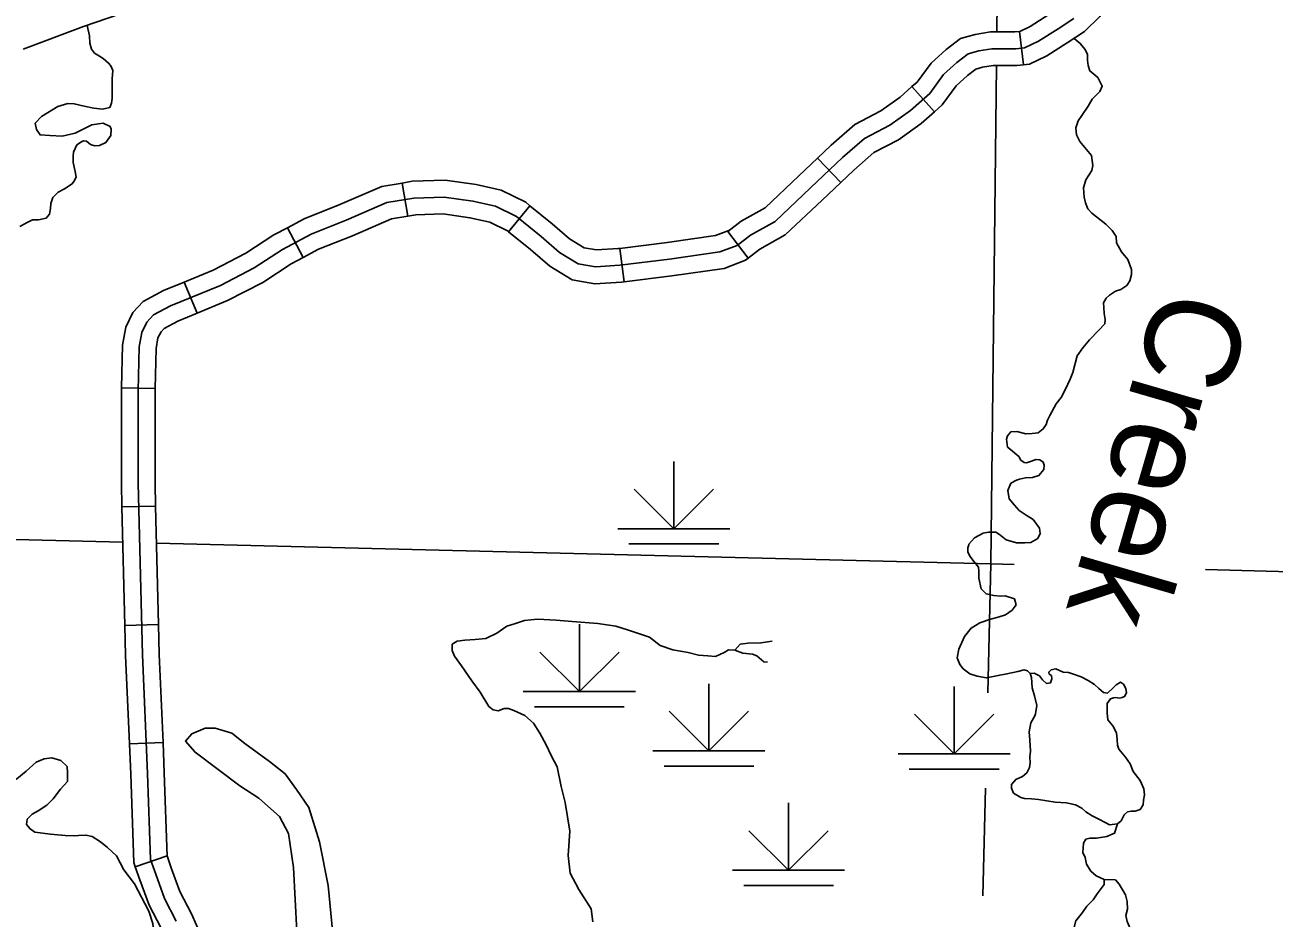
# Model space of a CAD drawing. Extents: x 8749 to 11879, y 13275 to 15339.
# Drawn here: x 10444.5 to 10555.9, y 13724.7 to 13804.4 of the extents above; entities that cross this region are included whole.
import ezdxf

# ---------------------------------------------------------------- set-up
doc = ezdxf.new("R2010")
doc.units = 0
for name, color, linetype in [('Level 15', 7, 'Continuous'), ('Level 32', 7, 'Continuous'), ('Level 35', 7, 'Continuous'), ('Level 44', 7, 'Continuous'), ('Level 5', 7, 'Continuous')]:
    doc.layers.add(name, color=color, linetype=linetype)

msp = doc.modelspace()

# ---------------------------------------------------------------- linework, layer by layer
at = {"layer": 'Level 15'}
for points in [[(10449.72, 13804.25), (10452.92, 13805.35), (10454.17, 13805.76)], [(10444.35, 13802.22), (10449.72, 13804.25)]]:
    msp.add_lwpolyline(points, dxfattribs=at)
at = {"layer": 'Level 32'}
for p, q in [((10533.55, 13800.84), (10533.2, 13803.82)), ((10525.6, 13796.65), (10523.6, 13798.89)), ((10517.25, 13790.35), (10515.18, 13792.52)), ((10478.64, 13787.34), (10478.14, 13790.29)), ((10487.63, 13785.94), (10489.53, 13788.27)), ((10469.31, 13783.66), (10467.9, 13786.3)), ((10509, 13783.59), (10507.17, 13785.97)), ((10497.92, 13781.48), (10497.55, 13784.46)), ((10459.86, 13778.68), (10458.71, 13781.46)), ((10456.11, 13771.95), (10453.11, 13772.02)), ((10456.15, 13761.46), (10453.15, 13761.39)), ((10456.4, 13750.9), (10453.4, 13750.83)), ((10456.81, 13740.38), (10453.81, 13740.25)), ((10457.18, 13730.26), (10454.34, 13729.29))]:
    msp.add_line(p, q, dxfattribs=at)
for points in [[(10533.2, 13803.82), (10533.22, 13803.82), (10534.15, 13804.27), (10535.81, 13805.32), (10537.1, 13806.15), (10538, 13807.04), (10538.52, 13807.87), (10539.06, 13809.4), (10539.13, 13809.7)], [(10533.55, 13800.84), (10534.07, 13800.9), (10535.61, 13801.64), (10537.43, 13802.79), (10538.98, 13803.8), (10540.35, 13805.14), (10541.24, 13806.55), (10541.94, 13808.55), (10542.05, 13809)], [(10523.6, 13798.89), (10524.06, 13799.3), (10525.3, 13800.99), (10526.65, 13802.19), (10527.92, 13803.18), (10529.24, 13803.55), (10530.6, 13803.77), (10531.68, 13803.77), (10532.78, 13803.77), (10533.2, 13803.82)], [(10525.6, 13796.65), (10526.29, 13797.27), (10527.53, 13798.96), (10528.56, 13799.88), (10529.3, 13800.45), (10529.9, 13800.62), (10530.83, 13800.77), (10531.68, 13800.77), (10532.95, 13800.77), (10533.55, 13800.84)], [(10515.18, 13792.52), (10516.39, 13793.67), (10518.51, 13795.5), (10520.82, 13796.72), (10522.55, 13797.95), (10523.6, 13798.89)], [(10517.25, 13790.35), (10518.4, 13791.44), (10520.21, 13793.01), (10522.39, 13794.16), (10524.42, 13795.6), (10525.6, 13796.65)], [(10507.17, 13785.97), (10508.37, 13786.89), (10510.5, 13788.09), (10513.52, 13790.94), (10515.18, 13792.52)], [(10478.14, 13790.29), (10479.03, 13790.45), (10481.97, 13790.55), (10484.72, 13790.15), (10486.96, 13789.64), (10489.15, 13788.57), (10489.53, 13788.27)], [(10467.9, 13786.3), (10469.39, 13787.1), (10472.57, 13788.37), (10476.33, 13789.99), (10478.14, 13790.29)], [(10509, 13783.59), (10510.03, 13784.38), (10512.29, 13785.66), (10515.59, 13788.76), (10517.25, 13790.35)], [(10489.53, 13788.27), (10491.5, 13786.66), (10493.07, 13785.31), (10494.37, 13784.51), (10495.47, 13784.32), (10497.4, 13784.44), (10497.55, 13784.46)], [(10469.31, 13783.66), (10470.66, 13784.38), (10473.71, 13785.59), (10477.19, 13787.09), (10478.64, 13787.34)], [(10478.64, 13787.34), (10479.34, 13787.45), (10481.8, 13787.54), (10484.18, 13787.2), (10485.96, 13786.79), (10487.53, 13786.03), (10487.63, 13785.94)], [(10458.71, 13781.46), (10461.29, 13782.52), (10464.19, 13784.02), (10466.7, 13785.66), (10467.9, 13786.3)], [(10487.63, 13785.94), (10489.57, 13784.36), (10491.3, 13782.88), (10493.29, 13781.66), (10495.31, 13781.3), (10497.68, 13781.45), (10497.92, 13781.48)], [(10497.55, 13784.46), (10501.78, 13784.98), (10506.09, 13785.6), (10507.28, 13786.06), (10507.17, 13785.97)], [(10459.86, 13778.68), (10462.56, 13779.8), (10465.7, 13781.42), (10468.23, 13783.08), (10469.31, 13783.66)], [(10497.92, 13781.48), (10502.18, 13782.01), (10506.85, 13782.68), (10508.76, 13783.41), (10509, 13783.59)], [(10453.11, 13772.02), (10453.2, 13775.83), (10453.48, 13777.44), (10454.13, 13778.75), (10455.05, 13779.73), (10456.85, 13780.69), (10458.71, 13781.46)], [(10456.11, 13771.95), (10456.19, 13775.53), (10456.36, 13776.49), (10456.63, 13777.02), (10456.9, 13777.32), (10458.12, 13777.97), (10459.86, 13778.68)], [(10453.15, 13761.39), (10453.1, 13763.48), (10453.1, 13771.76), (10453.11, 13772.02)], [(10456.15, 13761.46), (10456.1, 13763.51), (10456.1, 13771.73), (10456.11, 13771.95)], [(10456.4, 13750.9), (10456.15, 13761.46)], [(10453.4, 13750.83), (10453.15, 13761.39)], [(10453.81, 13740.25), (10453.47, 13748.14), (10453.4, 13750.83)], [(10456.81, 13740.38), (10456.47, 13748.24), (10456.4, 13750.9)], [(10457.19, 13730.23), (10456.92, 13737.66), (10456.81, 13740.38)], [(10454.34, 13729.29), (10454.21, 13729.67), (10453.93, 13737.54), (10453.81, 13740.25)], [(10461.26, 13720.6), (10460.7, 13722.05), (10459.34, 13725.1), (10458.31, 13727.07), (10457.57, 13729.12), (10457.18, 13730.26)], [(10458.46, 13719.52), (10457.93, 13720.9), (10456.64, 13723.8), (10455.56, 13725.86), (10454.74, 13728.12), (10454.34, 13729.29)]]:
    msp.add_lwpolyline(points, dxfattribs=at)
at = {"layer": 'Level 35'}
for points in [[(10457.99, 13724.45), (10456.94, 13726.47), (10456.16, 13728.62), (10455.7, 13729.95), (10455.43, 13737.6), (10454.97, 13748.19), (10454.6, 13763.5), (10454.6, 13771.74), (10454.69, 13775.68), (10454.92, 13776.97), (10455.38, 13777.88), (10455.97, 13778.53), (10457.49, 13779.33), (10461.93, 13781.16), (10464.95, 13782.72), (10467.46, 13784.37), (10470.03, 13785.74), (10473.14, 13786.98), (10476.76, 13788.54), (10479.18, 13788.95), (10481.88, 13789.04), (10484.45, 13788.68), (10486.46, 13788.22), (10488.34, 13787.3), (10490.54, 13785.51), (10492.18, 13784.09), (10493.83, 13783.08), (10495.39, 13782.81), (10497.54, 13782.95), (10501.98, 13783.5), (10506.47, 13784.14), (10508.02, 13784.73), (10509.2, 13785.64), (10511.4, 13786.87), (10514.56, 13789.85), (10517.39, 13792.56), (10519.36, 13794.25), (10521.61, 13795.44), (10523.48, 13796.77), (10525.18, 13798.28), (10526.41, 13799.98), (10527.6, 13801.03), (10528.61, 13801.81), (10529.57, 13802.09), (10530.72, 13802.27), (10531.68, 13802.27), (10532.87, 13802.27), (10533.64, 13802.36), (10534.88, 13802.96), (10536.62, 13804.06), (10538.04, 13804.97)], [(10452.11, 13795.32), (10451.48, 13795.62), (10450.46, 13795.49), (10448.99, 13794.74), (10447.81, 13794.47), (10446.72, 13794.52), (10445.84, 13794.59), (10445.52, 13795.07), (10445.42, 13795.62), (10445.97, 13796.24), (10447.44, 13797.12), (10448.31, 13797.39), (10448.89, 13797.37), (10449.79, 13797.14), (10450.64, 13796.97), (10451.41, 13796.87), (10452.06, 13797.02), (10452.21, 13797.42), (10452.26, 13797.84), (10452.26, 13798.57), (10452.26, 13799.59), (10452.33, 13800.34), (10452.16, 13800.74), (10451.96, 13800.99), (10451.48, 13801.39), (10451.14, 13801.62), (10450.71, 13801.87), (10450.44, 13802.22), (10450.29, 13802.77), (10450.26, 13803.42), (10450.04, 13804.36)], [(10538.74, 13796.33), (10539.3, 13797.15), (10539.68, 13797.76), (10540.36, 13798.47), (10540.56, 13798.92), (10540.16, 13799.71), (10539.47, 13800.29), (10539.3, 13800.77), (10539.25, 13801.25), (10539.25, 13801.79), (10539.02, 13802.24), (10538.61, 13802.75), (10538.06, 13803.2)], [(10540.89, 13786.62), (10539.65, 13787.59), (10539.27, 13788), (10539.07, 13788.51), (10538.94, 13789.04), (10538.89, 13789.87), (10539.09, 13790.58), (10539.65, 13791.42), (10539.73, 13791.85), (10539.6, 13792.74), (10539.17, 13793.29), (10538.56, 13794), (10538.26, 13794.59), (10538.21, 13795.22), (10538.41, 13795.85), (10538.74, 13796.33)], [(10448.97, 13791.33), (10448.81, 13792.12), (10448.81, 13792.39), (10448.81, 13792.69), (10448.84, 13793.04), (10449.11, 13793.69), (10449.54, 13793.97), (10449.71, 13794.07), (10449.99, 13794.02), (10450.34, 13793.72), (10450.74, 13793.62), (10451.14, 13793.64), (10451.71, 13793.92), (10452.16, 13794.52), (10452.18, 13795.09), (10452.11, 13795.32)], [(10444.03, 13786.41), (10444.68, 13786.76), (10445.18, 13787.01), (10445.7, 13787.01), (10446.4, 13787.16), (10446.7, 13787.51), (10446.77, 13788.01), (10446.8, 13788.46), (10446.97, 13789.01), (10447.47, 13789.48), (10448.02, 13789.76), (10448.7, 13790.21), (10448.87, 13790.43), (10449.07, 13790.81), (10448.97, 13791.33)], [(10537.7, 13772.79), (10537.93, 13773.39), (10538.33, 13774.86), (10538.84, 13775.6), (10539.42, 13776.31), (10540.26, 13777.17), (10540.79, 13777.73), (10540.82, 13778.13), (10540.74, 13778.64), (10540.71, 13779.19), (10540.69, 13779.6), (10540.92, 13780.03), (10541.22, 13780.28), (10541.75, 13780.64), (10542.21, 13780.79), (10542.76, 13781.15), (10543.02, 13781.58), (10543.17, 13782.13), (10543.17, 13782.59), (10542.84, 13783.48), (10542.28, 13784.16), (10541.85, 13784.97), (10541.8, 13785.53), (10541.45, 13786.06), (10540.89, 13786.62)], [(10535.88, 13769.55), (10536.46, 13770.59), (10536.89, 13771.17), (10537.3, 13771.91), (10537.7, 13772.79)], [(10533.13, 13765.89), (10532.39, 13766.51), (10532.13, 13766.74), (10532.03, 13767.45), (10532.11, 13767.75), (10532.41, 13768.08), (10532.94, 13768.13), (10533.75, 13767.93), (10534.31, 13767.96), (10534.84, 13768.01), (10535.3, 13768.36), (10535.55, 13768.74), (10535.68, 13769.12), (10535.88, 13769.55)], [(10532.75, 13753.18), (10531.91, 13753.45), (10531.53, 13753.43), (10530.9, 13753.5), (10530.21, 13753.63), (10529.78, 13754.09), (10529.56, 13755.05), (10529.56, 13755.66), (10529.53, 13756.01), (10529.15, 13756.49), (10528.75, 13757), (10528.59, 13757.38), (10528.57, 13757.74), (10528.67, 13758.01), (10528.67, 13758.07), (10529.18, 13758.65), (10529.94, 13759.05), (10530.42, 13759.13), (10530.72, 13759.15), (10531.08, 13759.15), (10531.4, 13758.93), (10531.99, 13758.47), (10532.92, 13758.19), (10533.66, 13758.19), (10534.19, 13758.22), (10534.82, 13758.57), (10535.02, 13759.03), (10534.97, 13759.51), (10534.42, 13760.27), (10533.78, 13760.67), (10533.15, 13761.08), (10532.75, 13761.54), (10532.26, 13762.12), (10532.14, 13762.85), (10532.42, 13763.51), (10532.92, 13763.79), (10533.2, 13763.87), (10533.71, 13763.99), (10534.34, 13764.02), (10534.92, 13764.2), (10535.35, 13764.73), (10535.4, 13765.11), (10535.3, 13765.39), (10535, 13765.59), (10534.64, 13765.64), (10534.26, 13765.49), (10533.81, 13765.34), (10533.61, 13765.36), (10533.3, 13765.56), (10533.13, 13765.89)], [(10531.29, 13746.35), (10530.23, 13746.14), (10529.4, 13746.3), (10528.77, 13746.5), (10528.17, 13746.95), (10527.86, 13747.35), (10527.64, 13747.94), (10527.79, 13748.69), (10528.29, 13749.83), (10528.87, 13750.58), (10529.65, 13751.06), (10530.59, 13751.39), (10531.29, 13751.57), (10531.95, 13751.77), (10532.53, 13752.17), (10532.88, 13752.65), (10532.75, 13753.18)], [(10482.6, 13749.14), (10483.03, 13749.43), (10483.71, 13749.51), (10484.64, 13749.56), (10485.6, 13749.66), (10486.58, 13750.14), (10487.46, 13750.75), (10488.24, 13751), (10489.05, 13751.25), (10489.61, 13751.33), (10490.21, 13751.38), (10491.87, 13751.28), (10493.29, 13751.18), (10495.58, 13751), (10497.19, 13750.77), (10498.23, 13750.42), (10500.19, 13749.76), (10501.15, 13749.03), (10502.28, 13748.63), (10503.65, 13748.4), (10504.55, 13748.17), (10505.38, 13748.12), (10506.07, 13748.05), (10506.85, 13748.4), (10507.25, 13748.65), (10507.8, 13748.6), (10508.51, 13748.35), (10509.39, 13748.27), (10509.75, 13748.12), (10510.4, 13747.57), (10510.7, 13747.54)], [(10507.8, 13748.6), (10508.28, 13749.16), (10508.99, 13749.23), (10510.12, 13749.26), (10511.13, 13749.43)], [(10491.41, 13739.22), (10490.97, 13740.16), (10490.42, 13741.22), (10489.86, 13742.1), (10489.08, 13742.79), (10488.1, 13743.24), (10487.62, 13743.42), (10487.24, 13743.42), (10486.71, 13743.19), (10486.26, 13743.29), (10485.86, 13743.59), (10485.1, 13744.88), (10484.34, 13745.89), (10483.44, 13747.23), (10482.81, 13748.08), (10482.6, 13748.59), (10482.6, 13749.14)], [(10541.9, 13740.61), (10541.85, 13741.23), (10541.5, 13741.86), (10541.07, 13742.39), (10541, 13743.02), (10541, 13743.86), (10541.3, 13744.26), (10541.58, 13744.36), (10541.75, 13744.38), (10542.1, 13744.33), (10542.33, 13744.38), (10542.56, 13744.49), (10542.74, 13744.81), (10542.68, 13745.19), (10542.46, 13745.57), (10542.18, 13745.75), (10541.8, 13745.52), (10541.5, 13745.22), (10541.02, 13744.79), (10540.67, 13744.84), (10540.26, 13745.19), (10539.86, 13745.55), (10539.31, 13745.9), (10538.7, 13746.23), (10538, 13746.48), (10537.57, 13746.61), (10537.09, 13746.66), (10536.43, 13746.96), (10536.01, 13746.86), (10535.8, 13746.66), (10535.83, 13746.48), (10536.03, 13746.35), (10536.06, 13746.05), (10535.95, 13745.7), (10535.6, 13745.65), (10535.25, 13745.97), (10534.97, 13746.33), (10534.49, 13746.55), (10534.14, 13746.53)], [(10534.62, 13742.93), (10534.74, 13743.68), (10534.52, 13744.54), (10534.32, 13745.24), (10534.27, 13746.18), (10534.14, 13746.53), (10533.89, 13746.76), (10533.61, 13746.86), (10533.03, 13746.71), (10532.07, 13746.5), (10531.29, 13746.35)], [(10534.16, 13739.6), (10534.11, 13740.59), (10534.06, 13741.34), (10534.19, 13742.12), (10534.54, 13742.75), (10534.62, 13742.93)], [(10466.31, 13738.67), (10464.11, 13740.3), (10462.96, 13741.2), (10461.46, 13741.65), (10460.56, 13741.65), (10459.37, 13741.15), (10458.82, 13740.5), (10459.67, 13739.5), (10463.66, 13736.5), (10465.36, 13735.42)], [(10541.93, 13733.13), (10542.25, 13733.4), (10542.53, 13733.93), (10542.83, 13734.18), (10543.14, 13734.25), (10543.51, 13734.25), (10543.94, 13734.41), (10544.22, 13734.83), (10544.24, 13735.24), (10544.32, 13735.72), (10544.27, 13736.25), (10543.94, 13737), (10543.31, 13737.79), (10543.06, 13738.47), (10542.63, 13739.07), (10542.05, 13739.78), (10541.93, 13740.13), (10541.9, 13740.61)], [(10491.41, 13739.22), (10491.97, 13738.21), (10492.32, 13736.44), (10492.67, 13735.03), (10493.08, 13732.46), (10492.93, 13730.29), (10493.13, 13728.72), (10493.88, 13727.26), (10494.99, 13725.55), (10495.14, 13724.38)], [(10536.36, 13735.04), (10534.89, 13735.29), (10534.26, 13735.34), (10533.63, 13735.39), (10533.31, 13735.47), (10532.65, 13735.87), (10532.47, 13736.3), (10532.47, 13736.63), (10532.85, 13737.08), (10533.46, 13737.33), (10533.83, 13737.66), (10534.09, 13738.14), (10534.14, 13738.57), (10534.11, 13739.1), (10534.16, 13739.6), (10534.19, 13739.63)], [(10444.65, 13733.06), (10444.7, 13733.53), (10445.15, 13733.98), (10445.67, 13734.28), (10446.45, 13734.78), (10447.02, 13735.36), (10447.67, 13736.2), (10448.3, 13736.9), (10448.3, 13737.68), (10448.27, 13738.23), (10447.7, 13738.78), (10446.9, 13739), (10446.2, 13738.93), (10445.5, 13738.63), (10444.6, 13737.83), (10443.78, 13737.15), (10442.8, 13736.68), (10441.88, 13736.6), (10441.06, 13736.63), (10440.36, 13736.65), (10439.76, 13736.8)], [(10468.45, 13729.23), (10468.75, 13723.53), (10468.1, 13717.28), (10467.41, 13713.88), (10467.56, 13712.38), (10468.4, 13711.73), (10469.45, 13711.78), (10471.05, 13713.13), (10472, 13717.13), (10472.15, 13721.13), (10471.55, 13727.63), (10470.75, 13731.52), (10469.8, 13734.57), (10468.7, 13736.17), (10467.7, 13737.57), (10466.31, 13738.67)], [(10468.45, 13729.23), (10468, 13732.27), (10467.21, 13733.77), (10465.36, 13735.42)], [(10541.93, 13733.13), (10541.2, 13733.04), (10540.94, 13733.19), (10540.14, 13733.6), (10539.68, 13733.83), (10539.1, 13734.2), (10538.75, 13734.53), (10538.17, 13734.81), (10537.77, 13734.91), (10537.39, 13734.99), (10536.86, 13735.01), (10536.36, 13735.04)], [(10446.79, 13732.19), (10445.38, 13732.38), (10444.95, 13732.66), (10444.65, 13733.06)], [(10540.74, 13728.14), (10540.01, 13728.48), (10539.56, 13728.89), (10539.15, 13729.52), (10539.03, 13730.12), (10538.83, 13730.55), (10538.88, 13731.41), (10539.1, 13731.74), (10539.46, 13731.84), (10540.06, 13731.84), (10540.97, 13731.99), (10541.67, 13732.29), (10541.93, 13733.13)], [(10456.03, 13719.34), (10455.43, 13720.6), (10455.32, 13721.8), (10455.56, 13722.94), (10455.81, 13723.54), (10455.93, 13723.89), (10455.9, 13724.22), (10455.53, 13725.32), (10454.28, 13727.77), (10453.31, 13729.02), (10452.66, 13730.27), (10451.86, 13731.01), (10451.24, 13731.51), (10450.48, 13731.98), (10449.94, 13732.11), (10449.26, 13732.08), (10448.94, 13732.06), (10448.09, 13732.08), (10446.79, 13732.19)], [(10537.97, 13723.55), (10538.22, 13724.48), (10538.8, 13725.22), (10539.18, 13725.77), (10539.76, 13726.33), (10540.11, 13726.88), (10540.74, 13727.71), (10540.74, 13728.14)], [(10541.75, 13728.12), (10540.74, 13728.14)], [(10544.19, 13716.77), (10544.87, 13718.1), (10545, 13718.61), (10545, 13719.01), (10544.9, 13719.39), (10544.7, 13719.67), (10544.52, 13720.14), (10544.47, 13720.4), (10544.47, 13721.48), (10544.37, 13722.06), (10544.04, 13722.59), (10543.59, 13723.02), (10543.18, 13723.53), (10542.78, 13724.41), (10542.68, 13724.94), (10542.83, 13725.52), (10542.78, 13726.2), (10542.63, 13726.78), (10542.35, 13727.29), (10542.07, 13727.74), (10541.75, 13728.12)]]:
    msp.add_lwpolyline(points, dxfattribs=at)
at = {"layer": 'Level 44'}
for p, q in [((10502.36, 13765.45), (10502.36, 13759.45)), ((10502.36, 13759.45), (10498.82, 13762.99)), ((10502.36, 13759.45), (10505.89, 13762.99)), ((10497.36, 13759.45), (10507.36, 13759.45)), ((10498.36, 13758.09), (10506.36, 13758.09)), ((10493.94, 13750.92), (10493.94, 13744.92)), ((10493.94, 13744.92), (10490.41, 13748.45)), ((10493.94, 13744.92), (10497.48, 13748.45)), ((10488.94, 13744.92), (10498.94, 13744.92)), ((10505.49, 13745.62), (10505.49, 13739.62)), ((10527.36, 13745.37), (10527.36, 13739.37)), ((10489.94, 13743.56), (10497.94, 13743.56)), ((10505.49, 13739.62), (10501.96, 13743.16)), ((10505.49, 13739.62), (10509.03, 13743.16)), ((10527.36, 13739.37), (10523.82, 13742.9)), ((10527.36, 13739.37), (10530.89, 13742.9)), ((10500.49, 13739.62), (10510.49, 13739.62)), ((10522.36, 13739.37), (10532.36, 13739.37)), ((10501.49, 13738.26), (10509.49, 13738.26)), ((10523.36, 13738.01), (10531.36, 13738.01)), ((10512.59, 13734.98), (10512.59, 13728.98)), ((10512.59, 13728.98), (10509.05, 13732.51)), ((10512.59, 13728.98), (10516.12, 13732.51)), ((10507.59, 13728.98), (10517.59, 13728.98)), ((10508.59, 13727.61), (10516.59, 13727.61))]:
    msp.add_line(p, q, dxfattribs=at)
at = {"layer": 'Level 5'}
for points in [[(10531.5, 13832.83), (10531.17, 13803.77)], [(10531.14, 13800.77), (10530.64, 13756.32)], [(10425.67, 13758.93), (10453.23, 13758.25)], [(10456.23, 13758.17), (10530.64, 13756.32)], [(10530.64, 13756.32), (10530.36, 13744.81)], [(10530.64, 13756.32), (10532.72, 13756.26)], [(10549.77, 13755.8), (10636.53, 13753.44)], [(10530.15, 13736.29), (10529.91, 13726.69)]]:
    msp.add_lwpolyline(points, dxfattribs=at)

# ---------------------------------------------------------------- texts
at = {"layer": 'Level 35'}
msp.add_text('Creek', height=8.448, rotation=253.7553, dxfattribs=at).set_placement((10545.77, 13781.27))

doc.saveas('drawing.dxf')
